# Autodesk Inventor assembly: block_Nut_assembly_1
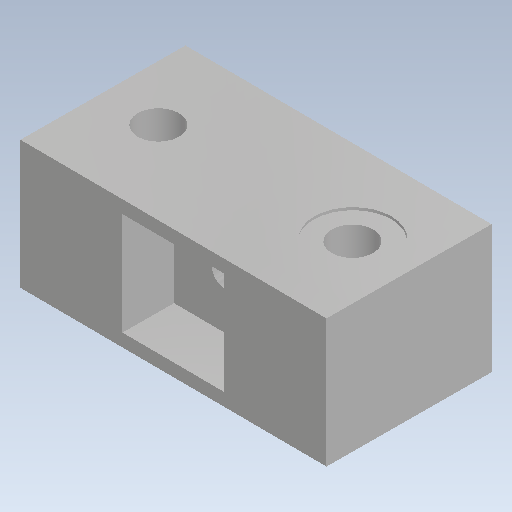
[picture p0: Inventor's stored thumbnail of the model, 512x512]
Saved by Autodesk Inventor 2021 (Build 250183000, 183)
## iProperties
Created: 2026-10
Part Number: block_Nut_assembly_1
Document SubType Name: Assembly
Designer: hp
Author: hp
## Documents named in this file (3)
- C:\Users\hp\Downloads\block_Nut_assembly_1.iam
- C:\Users\hp\Downloads\nut_Block_with_Bearing_1.ipt
- C:\Users\hp\Downloads\8mm_Bearing_1.ipt
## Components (2 placed, 2 different names)
1. nut_Block_with_Bearing:1
2. 8mm_Bearing:1
